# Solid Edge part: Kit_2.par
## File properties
Sűrűség: 0,000 kg/m^3
Pontosság: 0,990
Author: ahadarics
Last saved by: ahadarics
Revision: 76
Username: ahadarics
Dokumentum tartalom típus: 0
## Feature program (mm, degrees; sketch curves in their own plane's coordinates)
base feature "unnamed BaseFeature 1"
sketch for "Furat_1" plane through (0, 0, 7.75) normal (0, 0, 1) x-axis (-1, 0, 0)
  hole centre (0, 0) bore radius 4.283
hole "Furat_1" nominal diameter 9.728 finite  ThreadDepth = 7.5 mm
chamfer "Letörés_1" setback 0.7
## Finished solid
Body 1: solid body, 17 faces, 17 edges, 0 vertices.
  Faces by surface: cylinder 7, cone 5, plane 5
  Edges by curve: circle 17
Bounding box of the edges (mm): 30.000 x 30.000 x 23.500, from (-15, -15, -15.75) to (15, 15, 7.75).
Cylindrical faces by radius (mm): R1 x1, R4.28 x1, R4.283 x1, R11.45 x1, R12.5 x1, R13.5 x1, R15 x1
Conical faces (half-angle, radius in mm at the cone's reference point): 30 deg R12.4134 x1, 45 deg R4.983 x1, 45 deg R11.975 x1, 45 deg R14.75 x1, 59 deg R2.1415 x1
Planar faces by outward normal: +z 2, -z 3
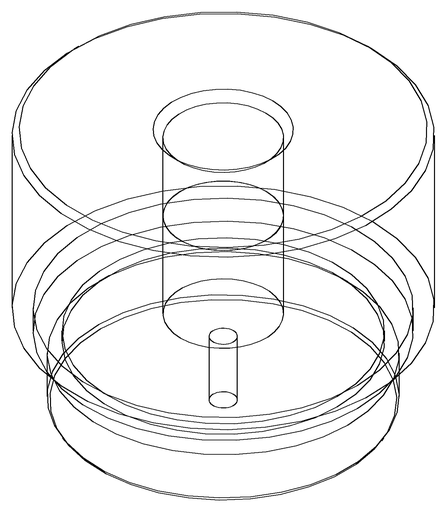
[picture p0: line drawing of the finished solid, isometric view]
